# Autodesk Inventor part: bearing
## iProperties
Created: 2009-01
Part Number: bearing
Document SubType Name: Modeling
Designer: pmulligan
Density: 1 g/cm^3
Author: pmulligan
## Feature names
1. Revolution1
